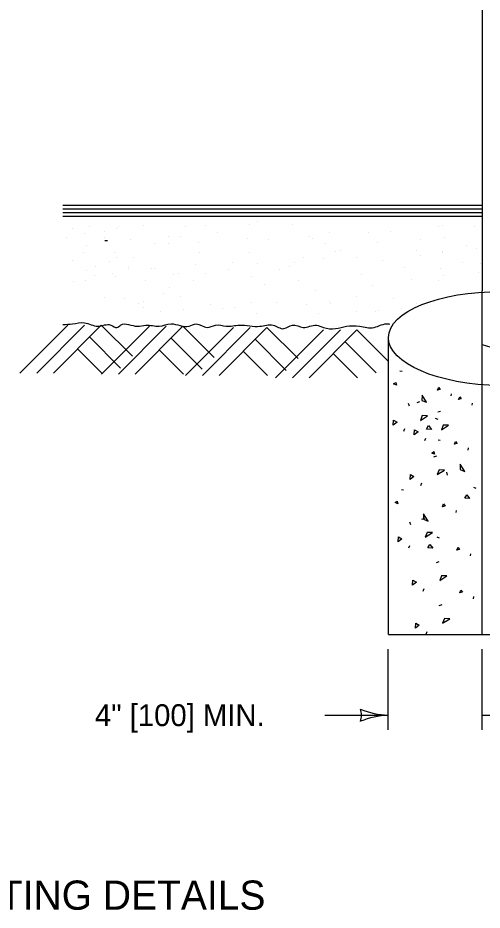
# Model space of a CAD drawing. Extents: x 49991.4 to 50021, y 49987.6 to 50011.4.
# Drawn here: x 50004.078 to 50005.351, y 49993.869 to 49996.314 of the extents above; entities that cross this region are included whole.
import ezdxf

# ---------------------------------------------------------------- set-up
doc = ezdxf.new("R2010")
doc.units = 0
for name, color, linetype in [('Level 1', 7, 'Continuous'), ('Level 2', 7, 'Continuous'), ('Level 3', 7, 'Continuous'), ('Level 4', 7, 'Continuous')]:
    doc.layers.add(name, color=color, linetype=linetype)

msp = doc.modelspace()

# ---------------------------------------------------------------- linework, layer by layer
at = {"layer": 'Level 1'}
for p, q in [((50005.3513, 49996.6693), (50005.3513, 49995.5658)), ((50004.2016, 49995.8006), (50005.3513, 49995.8006)), ((50004.2016, 49995.7906), (50005.3513, 49995.7906)), ((50004.2016, 49995.7806), (50005.3513, 49995.7806)), ((50004.2016, 49995.7706), (50005.3513, 49995.7706)), ((50004.2278, 49995.7356), (50004.2278, 49995.7356)), ((50004.2739, 49995.7422), (50004.2739, 49995.7422)), ((50004.3497, 49995.7356), (50004.3497, 49995.7356)), ((50004.353, 49995.7422), (50004.353, 49995.7422)), ((50004.4222, 49995.7455), (50004.4222, 49995.7455)), ((50004.5375, 49995.7422), (50004.5375, 49995.7422)), ((50004.5935, 49995.7455), (50004.5935, 49995.7455)), ((50004.7121, 49995.7488), (50004.7121, 49995.7488)), ((50004.7351, 49995.7554), (50004.7351, 49995.7554)), ((50004.8307, 49995.7488), (50004.8307, 49995.7488)), ((50005.2326, 49995.7422), (50005.2326, 49995.7422)), ((50005.2425, 49995.7455), (50005.2425, 49995.7455)), ((50005.3314, 49995.7422), (50005.3314, 49995.7422)), ((50004.2113, 49995.7125), (50004.2113, 49995.7125)), ((50004.2607, 49995.7224), (50004.2607, 49995.7224)), ((50004.3167, 49995.729), (50004.3167, 49995.729)), ((50004.3167, 49995.7125), (50004.3167, 49995.7125)), ((50004.4913, 49995.7158), (50004.4913, 49995.7158)), ((50004.5243, 49995.7158), (50004.5243, 49995.7158)), ((50004.6264, 49995.7257), (50004.6264, 49995.7257)), ((50004.7088, 49995.7092), (50004.7088, 49995.7092)), ((50004.8768, 49995.7158), (50004.8768, 49995.7158)), ((50004.8867, 49995.7092), (50004.8867, 49995.7092)), ((50004.9328, 49995.7257), (50004.9328, 49995.7257)), ((50005.0382, 49995.7257), (50005.0382, 49995.7257)), ((50005.1008, 49995.729), (50005.1008, 49995.729)), ((50005.2491, 49995.7125), (50005.2491, 49995.7125)), ((50004.2673, 49995.6895), (50004.2673, 49995.6895)), ((50004.3233, 49995.7027), (50004.3167, 49995.7027)), ((50004.3233, 49995.7027), (50004.3233, 49995.7027)), ((50004.3859, 49995.7059), (50004.3859, 49995.7059)), ((50004.4518, 49995.6961), (50004.4518, 49995.6961)), ((50004.4913, 49995.6961), (50004.4913, 49995.6961)), ((50004.5737, 49995.6994), (50004.5737, 49995.6994)), ((50004.7648, 49995.7059), (50004.7648, 49995.7059)), ((50004.9229, 49995.6961), (50004.9229, 49995.6961)), ((50005.0646, 49995.6994), (50005.0646, 49995.6994)), ((50005.1832, 49995.7059), (50005.1832, 49995.7059)), ((50005.3084, 49995.6895), (50005.3084, 49995.6895)), ((50004.2574, 49995.6697), (50004.2574, 49995.6697)), ((50004.3431, 49995.6697), (50004.3431, 49995.6697)), ((50004.577, 49995.6697), (50004.577, 49995.6697)), ((50004.7121, 49995.6697), (50004.7121, 49995.6697)), ((50004.9493, 49995.673), (50004.9493, 49995.673)), ((50004.9624, 49995.6763), (50004.9624, 49995.6763)), ((50005.17, 49995.6763), (50005.17, 49995.6763)), ((50005.1832, 49995.6631), (50005.1832, 49995.6631)), ((50005.2425, 49995.673), (50005.2425, 49995.673)), ((50005.2425, 49995.6697), (50005.2425, 49995.6697)), ((50005.3347, 49995.6829), (50005.3347, 49995.6829)), ((50004.2278, 49995.6499), (50004.2278, 49995.6499)), ((50004.3299, 49995.6466), (50004.3299, 49995.6466)), ((50004.3497, 49995.6565), (50004.3497, 49995.6565)), ((50004.3958, 49995.6565), (50004.3958, 49995.6565)), ((50004.5638, 49995.6368), (50004.5638, 49995.6368)), ((50004.6659, 49995.6434), (50004.6659, 49995.6434)), ((50004.7351, 49995.6401), (50004.7351, 49995.6401)), ((50004.8373, 49995.6434), (50004.8373, 49995.6434)), ((50004.8603, 49995.6565), (50004.8603, 49995.6565)), ((50004.9163, 49995.6532), (50004.9163, 49995.6532)), ((50005.0053, 49995.6565), (50005.0053, 49995.6565)), ((50005.0777, 49995.6499), (50005.0777, 49995.6499)), ((50005.2985, 49995.6434), (50005.2985, 49995.6434)), ((50005.3479, 49995.6401), (50005.3479, 49995.6401)), ((50004.2673, 49995.6203), (50004.2673, 49995.6203)), ((50004.2904, 49995.6335), (50004.2904, 49995.6335)), ((50004.3365, 49995.6137), (50004.3365, 49995.6137)), ((50004.3826, 49995.6335), (50004.3826, 49995.6335)), ((50004.3826, 49995.6269), (50004.3826, 49995.6269)), ((50004.4452, 49995.6269), (50004.4452, 49995.6269)), ((50004.4518, 49995.6269), (50004.4518, 49995.6269)), ((50004.5177, 49995.6137), (50004.5177, 49995.6137)), ((50004.5935, 49995.6137), (50004.5935, 49995.6137)), ((50004.6561, 49995.6236), (50004.6561, 49995.6236)), ((50004.7944, 49995.6236), (50004.7944, 49995.6236)), ((50004.8241, 49995.6335), (50004.8241, 49995.6335)), ((50005.137, 49995.6302), (50005.137, 49995.6302)), ((50005.2359, 49995.6269), (50005.2359, 49995.6269)), ((50005.3413, 49995.617), (50005.3413, 49995.617)), ((50004.2311, 49995.5906), (50004.2311, 49995.5906)), ((50004.264, 49995.5939), (50004.264, 49995.5939)), ((50004.2871, 49995.6071), (50004.2871, 49995.6071)), ((50004.3464, 49995.6038), (50004.3464, 49995.6038)), ((50004.4287, 49995.5939), (50004.4287, 49995.5939)), ((50004.5045, 49995.6104), (50004.5045, 49995.6104)), ((50004.5605, 49995.5939), (50004.5605, 49995.5939)), ((50004.7187, 49995.6038), (50004.7187, 49995.6038)), ((50004.8471, 49995.5939), (50004.8471, 49995.5939)), ((50005.0217, 49995.6104), (50005.0217, 49995.6104)), ((50005.1568, 49995.5972), (50005.1568, 49995.5972)), ((50005.2326, 49995.5939), (50005.2326, 49995.5939)), ((50005.2458, 49995.6071), (50005.2458, 49995.6071)), ((50004.4946, 49995.5742), (50004.4946, 49995.5742)), ((50004.7549, 49995.5841), (50004.7549, 49995.5841)), ((50004.8933, 49995.5676), (50004.8933, 49995.5676)), ((50005.0514, 49995.5808), (50005.0514, 49995.5808)), ((50005.3513, 49995.4192), (50005.3513, 49995.5658)), ((50004.3167, 49995.5478), (50004.3167, 49995.5478)), ((50004.3694, 49995.5445), (50004.3694, 49995.5445)), ((50004.4782, 49995.5577), (50004.4782, 49995.5577)), ((50004.5243, 49995.5511), (50004.5243, 49995.5511)), ((50005.0053, 49995.5511), (50005.0053, 49995.5511)), ((50005.1074, 49995.5445), (50005.1074, 49995.5445)), ((50004.409, 49995.5313), (50004.409, 49995.5313)), ((50004.4222, 49995.5379), (50004.4222, 49995.5379)), ((50004.4222, 49995.5215), (50004.4222, 49995.5215)), ((50004.5309, 49995.5149), (50004.5309, 49995.5149)), ((50004.6066, 49995.5281), (50004.6066, 49995.5281)), ((50004.6396, 49995.5182), (50004.6396, 49995.5182)), ((50004.6725, 49995.5215), (50004.6725, 49995.5215)), ((50004.7187, 49995.5346), (50004.7187, 49995.5346)), ((50004.7878, 49995.5346), (50004.7878, 49995.5346)), ((50004.8702, 49995.5281), (50004.8702, 49995.5281)), ((50004.9328, 49995.5379), (50004.9328, 49995.5379)), ((50004.9361, 49995.5313), (50004.9361, 49995.5313)), ((50005.1305, 49995.5182), (50005.1305, 49995.5182)), ((50005.17, 49995.5313), (50005.17, 49995.5313)), ((50004.4683, 49995.5083), (50004.4683, 49995.5083)), ((50004.4683, 49995.5083), (50004.4683, 49995.5083)), ((50004.7318, 49995.505), (50004.7318, 49995.505)), ((50004.9031, 49995.505), (50004.9031, 49995.505)), ((50005.0053, 49995.5083), (50005.0053, 49995.5083)), ((50005.058, 49995.5083), (50005.058, 49995.5083)), ((50005.0679, 49995.5116), (50005.0679, 49995.5116)), ((50004.0835, 49995.3406), (50004.2146, 49995.472)), ((50004.1299, 49995.3406), (50004.261, 49995.472)), ((50004.1753, 49995.3406), (50004.3064, 49995.472)), ((50004.3064, 49995.472), (50004.3922, 49995.3865)), ((50004.3075, 49995.3374), (50004.4386, 49995.4688)), ((50004.3539, 49995.3374), (50004.485, 49995.4688)), ((50004.3993, 49995.3374), (50004.5304, 49995.4688)), ((50004.5304, 49995.4688), (50004.6162, 49995.3833)), ((50004.5379, 49995.3341), (50004.669, 49995.4655)), ((50004.5843, 49995.3341), (50004.7154, 49995.4655)), ((50004.6297, 49995.3341), (50004.7608, 49995.4655)), ((50004.7608, 49995.4655), (50004.8466, 49995.38)), ((50004.9427, 49995.4688), (50004.9427, 49995.4688)), ((50004.7849, 49995.3275), (50004.916, 49995.4589)), ((50004.8313, 49995.3275), (50004.9624, 49995.4589)), ((50004.8767, 49995.3275), (50005.0078, 49995.4589)), ((50005.0078, 49995.4589), (50005.0936, 49995.3734)), ((50004.274, 49995.4396), (50004.3595, 49995.3542)), ((50004.498, 49995.4364), (50004.5835, 49995.351)), ((50004.7284, 49995.4331), (50004.8139, 49995.3477)), ((50004.9754, 49995.4265), (50005.0609, 49995.3411)), ((50005.0942, 49994.6238), (50005.0944, 49995.4365)), ((50004.2416, 49995.4069), (50004.3081, 49995.3406)), ((50004.4656, 49995.4037), (50004.5321, 49995.3374)), ((50004.696, 49995.4004), (50004.7625, 49995.3341)), ((50004.943, 49995.3938), (50005.0095, 49995.3275)), ((50005.1317, 49995.3452), (50005.1259, 49995.3459)), ((50005.1082, 49995.3107), (50005.1141, 49995.3147)), ((50005.1159, 49995.3074), (50005.1082, 49995.3107)), ((50005.1141, 49995.3147), (50005.1159, 49995.3074)), ((50005.2289, 49995.294), (50005.2322, 49995.3017)), ((50005.2362, 49995.2958), (50005.2289, 49995.294)), ((50005.2322, 49995.3017), (50005.2362, 49995.2958)), ((50005.1865, 49995.2802), (50005.1861, 49995.2655)), ((50005.199, 49995.2604), (50005.1865, 49995.2802)), ((50005.2667, 49995.2782), (50005.2674, 49995.284)), ((50005.2864, 49995.2679), (50005.2897, 49995.2756)), ((50005.2937, 49995.2697), (50005.2864, 49995.2679)), ((50005.2897, 49995.2756), (50005.2937, 49995.2697)), ((50005.1483, 49995.2581), (50005.1508, 49995.2504)), ((50005.1796, 49995.2616), (50005.1719, 49995.2591)), ((50005.1861, 49995.2655), (50005.199, 49995.2604)), ((50005.3242, 49995.2521), (50005.3249, 49995.2579)), ((50005.187, 49995.2238), (50005.1819, 49995.2109)), ((50005.1819, 49995.2109), (50005.2017, 49995.2234)), ((50005.2017, 49995.2234), (50005.187, 49995.2238)), ((50005.2371, 49995.2355), (50005.2294, 49995.233)), ((50005.1076, 49995.1977), (50005.1084, 49995.2113)), ((50005.1179, 49995.2058), (50005.1076, 49995.1977)), ((50005.1084, 49995.2113), (50005.1179, 49995.2058)), ((50005.1986, 49995.1869), (50005.2041, 49995.1964)), ((50005.2041, 49995.1964), (50005.2122, 49995.1861)), ((50005.2225, 49995.217), (50005.2294, 49995.2144)), ((50005.2445, 49995.1977), (50005.2394, 49995.1848)), ((50005.2394, 49995.1848), (50005.2592, 49995.1973)), ((50005.2592, 49995.1973), (50005.2445, 49995.1977)), ((50005.1385, 49995.1874), (50005.1359, 49995.1805)), ((50005.1651, 49995.1716), (50005.1659, 49995.1852)), ((50005.1754, 49995.1797), (50005.1651, 49995.1716)), ((50005.1659, 49995.1852), (50005.1754, 49995.1797)), ((50005.2122, 49995.1861), (50005.1986, 49995.1869)), ((50005.196, 49995.1613), (50005.1934, 49995.1544)), ((50005.2365, 49995.1558), (50005.2307, 49995.1565)), ((50005.2752, 49995.1453), (50005.2785, 49995.153)), ((50005.2825, 49995.1471), (50005.2752, 49995.1453)), ((50005.2785, 49995.153), (50005.2825, 49995.1471)), ((50005.213, 49995.1213), (50005.2189, 49995.1253)), ((50005.2189, 49995.1253), (50005.2207, 49995.118)), ((50005.313, 49995.1295), (50005.3137, 49995.1353)), ((50005.2207, 49995.118), (50005.213, 49995.1213)), ((50005.2259, 49995.1129), (50005.2182, 49995.1104)), ((50005.2333, 49995.0751), (50005.2282, 49995.0622)), ((50005.2282, 49995.0622), (50005.248, 49995.0747)), ((50005.248, 49995.0747), (50005.2333, 49995.0751)), ((50005.2913, 49995.0908), (50005.2909, 49995.0761)), ((50005.2909, 49995.0761), (50005.3038, 49995.071)), ((50005.3038, 49995.071), (50005.2913, 49995.0908)), ((50005.1539, 49995.049), (50005.1547, 49995.0626)), ((50005.1642, 49995.0571), (50005.1539, 49995.049)), ((50005.1547, 49995.0626), (50005.1642, 49995.0571)), ((50005.2531, 49995.0687), (50005.2556, 49995.061)), ((50005.1848, 49995.0387), (50005.1822, 49995.0318)), ((50005.3273, 49995.0276), (50005.3342, 49995.025)), ((50005.1358, 49995.0198), (50005.13, 49995.0205)), ((50005.3034, 49994.9975), (50005.3089, 49995.007)), ((50005.3089, 49995.007), (50005.317, 49994.9967)), ((50005.1123, 49994.9853), (50005.1182, 49994.9893)), ((50005.12, 49994.982), (50005.1123, 49994.9853)), ((50005.1182, 49994.9893), (50005.12, 49994.982)), ((50005.2423, 49994.974), (50005.2456, 49994.9817)), ((50005.2496, 49994.9758), (50005.2423, 49994.974)), ((50005.2456, 49994.9817), (50005.2496, 49994.9758)), ((50005.317, 49994.9967), (50005.3034, 49994.9975)), ((50005.1906, 49994.9548), (50005.1902, 49994.9401)), ((50005.2031, 49994.935), (50005.1906, 49994.9548)), ((50005.2801, 49994.9582), (50005.2808, 49994.964)), ((50005.1524, 49994.9327), (50005.1549, 49994.925)), ((50005.193, 49994.9416), (50005.1853, 49994.9391)), ((50005.1902, 49994.9401), (50005.2031, 49994.935)), ((50005.2004, 49994.9038), (50005.1953, 49994.8909)), ((50005.1953, 49994.8909), (50005.2151, 49994.9034)), ((50005.2151, 49994.9034), (50005.2004, 49994.9038)), ((50005.121, 49994.8777), (50005.1218, 49994.8913)), ((50005.1313, 49994.8858), (50005.121, 49994.8777)), ((50005.1218, 49994.8913), (50005.1313, 49994.8858)), ((50005.2266, 49994.8916), (50005.2335, 49994.889)), ((50005.1519, 49994.8674), (50005.1493, 49994.8605)), ((50005.2027, 49994.8615), (50005.2082, 49994.871)), ((50005.2163, 49994.8607), (50005.2027, 49994.8615)), ((50005.2082, 49994.871), (50005.2163, 49994.8607)), ((50005.2818, 49994.8554), (50005.2851, 49994.8631)), ((50005.2891, 49994.8572), (50005.2818, 49994.8554)), ((50005.2851, 49994.8631), (50005.2891, 49994.8572)), ((50005.3196, 49994.8396), (50005.3203, 49994.8454)), ((50005.2325, 49994.823), (50005.2248, 49994.8205)), ((50005.2399, 49994.7852), (50005.2348, 49994.7723)), ((50005.2348, 49994.7723), (50005.2546, 49994.7848)), ((50005.2546, 49994.7848), (50005.2399, 49994.7852)), ((50005.1605, 49994.7591), (50005.1613, 49994.7727)), ((50005.1708, 49994.7672), (50005.1605, 49994.7591)), ((50005.1613, 49994.7727), (50005.1708, 49994.7672)), ((50005.1914, 49994.7488), (50005.1888, 49994.7419)), ((50005.2899, 49994.7379), (50005.2932, 49994.7456)), ((50005.2972, 49994.7397), (50005.2899, 49994.7379)), ((50005.2932, 49994.7456), (50005.2972, 49994.7397)), ((50005.3277, 49994.7221), (50005.3284, 49994.7279)), ((50005.2406, 49994.7055), (50005.2329, 49994.703)), ((50005.248, 49994.6677), (50005.2429, 49994.6548)), ((50005.2429, 49994.6548), (50005.2627, 49994.6673)), ((50005.2627, 49994.6673), (50005.248, 49994.6677)), ((50005.1686, 49994.6416), (50005.1694, 49994.6552)), ((50005.1789, 49994.6497), (50005.1686, 49994.6416)), ((50005.1694, 49994.6552), (50005.1789, 49994.6497)), ((50005.0942, 49994.6238), (50005.7105, 49994.6238)), ((50005.1995, 49994.6313), (50005.1969, 49994.6244))]:
    msp.add_line(p, q, dxfattribs=at)
msp.add_arc((50005.3989, 49995.5264), 0.1173, 246.0598, 293.9409, dxfattribs=at)
msp.add_ellipse((50005.4024, 49995.4348), major_axis=(0.3081, -0.0032), ratio=0.417147, dxfattribs=at)
msp.add_spline([(50004.2016, 49995.4736), (50004.2278, 49995.4753), (50004.2607, 49995.4786), (50004.297, 49995.4688), (50004.3332, 49995.472), (50004.3497, 49995.4655), (50004.3596, 49995.472), (50004.4057, 49995.4688), (50004.4287, 49995.472), (50004.465, 49995.4688), (50004.4979, 49995.4753), (50004.5473, 49995.4688), (50004.5671, 49995.4753), (50004.5968, 49995.4655), (50004.6198, 49995.472), (50004.6495, 49995.4688), (50004.6857, 49995.472), (50004.7417, 49995.4688), (50004.778, 49995.472), (50004.8076, 49995.4622), (50004.8307, 49995.472), (50004.8603, 49995.4655), (50004.8966, 49995.472), (50004.9163, 49995.4655), (50004.9493, 49995.4622), (50004.9789, 49995.4688), (50005.0151, 49995.4688), (50005.0547, 49995.4655), (50005.0942, 49995.4753), (50005.0972, 49995.4746)], degree=3, dxfattribs=at)
at = {"layer": 'Level 3'}
for p, q in [((50005.0935, 49994.3628), (50005.0935, 49994.5838)), ((50005.3513, 49994.3628), (50005.3513, 49994.5838)), ((50004.9201, 49994.4028), (50005.0935, 49994.4028)), ((50005.3513, 49994.4028), (50005.5247, 49994.4028))]:
    msp.add_line(p, q, dxfattribs=at)
for centre, radius, start, end in [((50005.1027, 49994.6249), 0.2223, 247.456, 267.6395), ((50004.9653, 49994.4028), 0.0548, 342.1388, 17.8612), ((50005.105, 49994.1701), 0.233, 92.8273, 112.0772)]:
    msp.add_arc(centre, radius, start, end, dxfattribs=at)
at = {"layer": 'Level 4'}
msp.add_line((50005.3513, 49994.6238), (50005.3513, 49995.4192), dxfattribs=at)

# ---------------------------------------------------------------- texts
at = {"layer": 'Level 2'}
for s, height, p in [('4" [100] MIN.', 0.06, (50004.2893, 49994.3728)), ('BREAKAWAY AND FOOTING DETAILS', 0.08, (50002.831, 49993.8697))]:
    msp.add_text(s, height=height, dxfattribs=at).set_placement(p)

doc.saveas('drawing.dxf')
